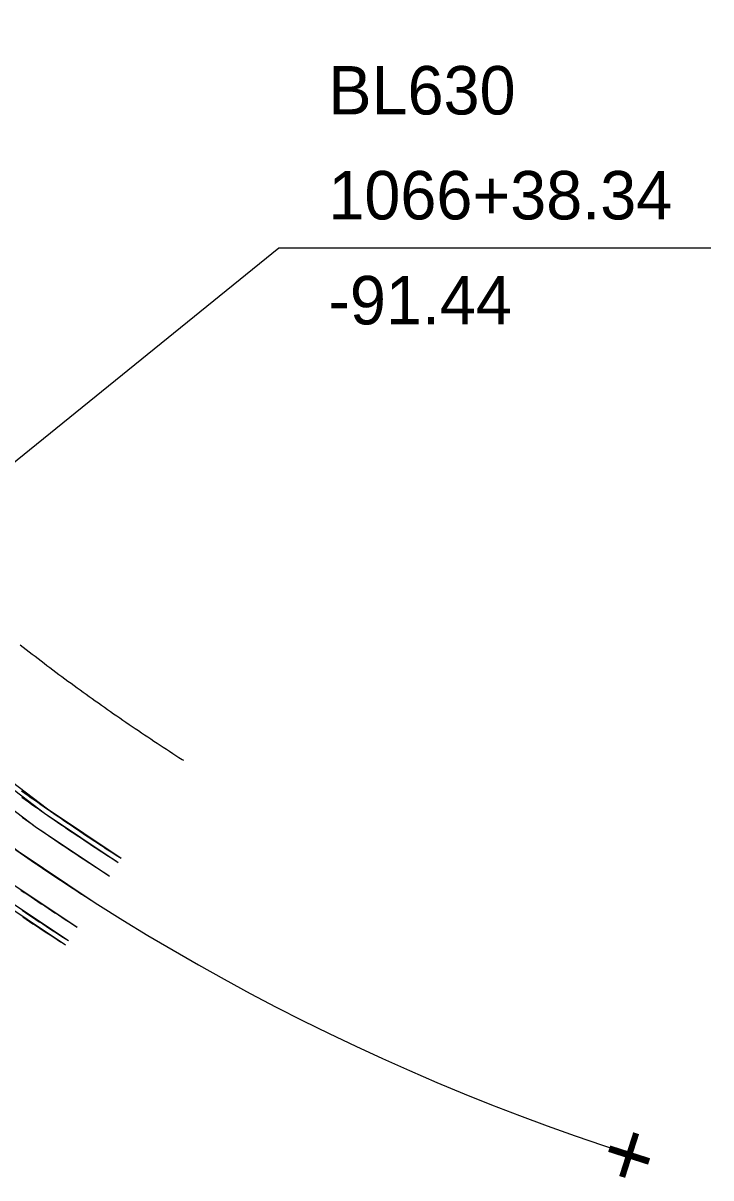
# Model space of a CAD drawing. Extents: x 1195880 to 1289360, y 2059330 to 2086925.
# Drawn here: x 1198545.2 to 1198715.7, y 2069821.4 to 2070107.4 of the extents above; entities that cross this region are included whole.
import ezdxf

# ---------------------------------------------------------------- set-up
doc = ezdxf.new("R2010")
doc.units = 0
for name, color, linetype in [('1', 7, 'Continuous'), ('20', 7, 'Continuous'), ('30', 7, 'Continuous'), ('Pavement', 7, 'Continuous')]:
    doc.layers.add(name, color=color, linetype=linetype)

msp = doc.modelspace()

# ---------------------------------------------------------------- linework, layer by layer
msp.add_line((1198620.61, 2070051.8), (1198715.67, 2070051.8))
msp.add_lwpolyline([(1198483.64, 2069950.58), (1198608.61, 2070051.8), (1198620.61, 2070051.8)])
at = {"layer": '1'}
msp.add_arc((1198871.12, 2070372.64), 572.96, 205.48475, 252.21121, dxfattribs=at)
at = {"layer": '30'}
for points in [[(1198544.51, 2069953.4), (1198545.24, 2069952.83), (1198545.98, 2069952.26), (1198546.71, 2069951.7), (1198547.45, 2069951.13), (1198548.18, 2069950.57), (1198548.92, 2069950.01), (1198549.66, 2069949.44), (1198550.4, 2069948.88), (1198551.14, 2069948.32), (1198551.88, 2069947.77), (1198552.62, 2069947.21), (1198553.36, 2069946.65), (1198554.11, 2069946.1), (1198554.85, 2069945.55), (1198555.6, 2069945), (1198556.34, 2069944.45), (1198557.09, 2069943.9), (1198557.84, 2069943.35), (1198558.59, 2069942.8), (1198559.34, 2069942.26), (1198560.09, 2069941.72), (1198560.85, 2069941.17), (1198561.6, 2069940.63), (1198562.35, 2069940.09), (1198563.11, 2069939.55), (1198563.87, 2069939.02), (1198564.62, 2069938.48), (1198565.38, 2069937.95), (1198566.14, 2069937.42), (1198566.9, 2069936.88), (1198567.66, 2069936.35), (1198568.42, 2069935.82), (1198569.19, 2069935.3), (1198569.95, 2069934.77), (1198570.71, 2069934.25), (1198571.48, 2069933.72), (1198572.25, 2069933.2), (1198573.01, 2069932.68), (1198573.78, 2069932.16), (1198574.55, 2069931.64), (1198575.32, 2069931.12), (1198576.09, 2069930.61), (1198576.87, 2069930.09), (1198577.64, 2069929.58), (1198578.41, 2069929.07), (1198579.19, 2069928.56), (1198579.96, 2069928.05), (1198580.74, 2069927.54), (1198581.52, 2069927.04), (1198582.29, 2069926.53), (1198583.07, 2069926.03), (1198583.85, 2069925.53), (1198584.63, 2069925.03), (1198584.97, 2069924.81)], [(1198544.85, 2069917.26), (1198545.65, 2069916.69), (1198546.44, 2069916.12), (1198547.24, 2069915.55), (1198548.04, 2069914.99), (1198548.84, 2069914.43), (1198549.64, 2069913.86), (1198550.44, 2069913.3), (1198551.24, 2069912.74), (1198552.04, 2069912.19), (1198552.85, 2069911.63), (1198553.65, 2069911.08), (1198554.46, 2069910.52), (1198555.27, 2069909.97), (1198556.07, 2069909.42), (1198556.88, 2069908.87), (1198557.69, 2069908.32), (1198558.5, 2069907.78), (1198559.32, 2069907.23), (1198560.13, 2069906.69), (1198560.94, 2069906.15), (1198561.76, 2069905.61), (1198562.57, 2069905.07), (1198563.39, 2069904.53), (1198564.21, 2069903.99), (1198565.02, 2069903.46), (1198565.84, 2069902.92), (1198566.66, 2069902.39), (1198567.49, 2069901.86), (1198568.31, 2069901.33), (1198569.13, 2069900.8), (1198569.48, 2069900.58)], [(1198544.92, 2069915.67), (1198545.72, 2069915.1), (1198546.52, 2069914.53), (1198547.32, 2069913.97), (1198548.12, 2069913.4), (1198548.92, 2069912.84), (1198549.72, 2069912.28), (1198550.53, 2069911.72), (1198551.33, 2069911.16), (1198552.14, 2069910.6), (1198552.94, 2069910.04), (1198553.75, 2069909.49), (1198554.56, 2069908.94), (1198555.37, 2069908.38), (1198556.18, 2069907.83), (1198556.99, 2069907.29), (1198557.81, 2069906.74), (1198558.62, 2069906.19), (1198559.43, 2069905.65), (1198560.25, 2069905.1), (1198561.07, 2069904.56), (1198561.88, 2069904.02), (1198562.7, 2069903.48), (1198563.52, 2069902.94), (1198564.34, 2069902.41), (1198565.16, 2069901.87), (1198565.98, 2069901.34), (1198566.81, 2069900.81), (1198567.63, 2069900.28), (1198568.46, 2069899.75), (1198568.81, 2069899.52)], [(1198544.97, 2069887.66), (1198545.82, 2069887.09), (1198546.67, 2069886.52), (1198547.52, 2069885.96), (1198548.37, 2069885.39), (1198549.22, 2069884.83), (1198550.07, 2069884.27), (1198550.92, 2069883.71), (1198551.78, 2069883.15), (1198552.63, 2069882.6), (1198553.49, 2069882.04), (1198554.35, 2069881.49), (1198555.2, 2069880.93), (1198556.06, 2069880.38), (1198556.43, 2069880.15)], [(1198545.12, 2069886.05), (1198545.97, 2069885.48), (1198546.82, 2069884.91), (1198547.67, 2069884.34), (1198548.53, 2069883.78), (1198549.38, 2069883.22), (1198550.23, 2069882.66), (1198551.09, 2069882.1), (1198551.95, 2069881.54), (1198552.8, 2069880.98), (1198553.66, 2069880.43), (1198554.52, 2069879.88), (1198555.38, 2069879.32), (1198555.75, 2069879.09)]]:
    msp.add_lwpolyline(points, dxfattribs=at)
at = {"layer": 'Pavement'}
for points in [[(1198303.05, 2070269.36), (1198317.28, 2070222.18), (1198337.85, 2070177.24), (1198359.37, 2070132.1), (1198382.31, 2070088.38), (1198408.94, 2070046.86), (1198439.09, 2070007.82), (1198472.53, 2069971.56), (1198509.01, 2069938.34), (1198548.24, 2069908.44), (1198566.66, 2069896.15)], [(1198303.06, 2070269.36), (1198317.28, 2070222.18), (1198337.86, 2070177.24), (1198359.37, 2070132.1), (1198382.31, 2070088.38), (1198408.94, 2070046.86), (1198439.1, 2070007.82), (1198472.54, 2069971.56), (1198509.01, 2069938.34), (1198548.24, 2069908.44), (1198566.66, 2069896.15)], [(1198306.9, 2070270.46), (1198321.01, 2070223.63), (1198341.47, 2070178.96), (1198362.98, 2070133.82), (1198385.77, 2070090.4), (1198412.21, 2070049.17), (1198442.15, 2070010.4), (1198475.36, 2069974.39), (1198511.57, 2069941.42), (1198550.52, 2069911.72), (1198568.81, 2069899.52)], [(1198308.1, 2070270.81), (1198322.17, 2070224.08), (1198342.59, 2070179.5), (1198364.11, 2070134.36), (1198386.85, 2070091.02), (1198413.23, 2070049.89), (1198443.11, 2070011.21), (1198476.24, 2069975.28), (1198512.37, 2069942.38), (1198551.24, 2069912.75), (1198569.48, 2069900.58)], [(1198295.84, 2070267.29), (1198310.29, 2070219.47), (1198331.08, 2070174.01), (1198352.6, 2070128.87), (1198375.82, 2070084.61), (1198402.81, 2070042.54), (1198433.36, 2070002.98), (1198467.25, 2069966.24), (1198504.21, 2069932.58), (1198543.96, 2069902.28), (1198562.62, 2069889.83)], [(1198283.59, 2070263.78), (1198298.41, 2070214.85), (1198319.58, 2070168.52), (1198341.09, 2070123.39), (1198364.8, 2070078.21), (1198392.39, 2070035.2), (1198423.62, 2069994.76), (1198458.26, 2069957.19), (1198496.04, 2069922.79), (1198536.68, 2069891.81), (1198555.75, 2069879.09)], [(1198284.79, 2070264.13), (1198299.57, 2070215.3), (1198320.71, 2070169.06), (1198342.22, 2070123.93), (1198365.89, 2070078.84), (1198393.42, 2070035.92), (1198424.58, 2069995.57), (1198459.14, 2069958.08), (1198496.84, 2069923.75), (1198537.39, 2069892.84), (1198556.43, 2069880.14)], [(1198288.63, 2070265.23), (1198303.3, 2070216.75), (1198324.31, 2070170.78), (1198345.83, 2070125.65), (1198369.34, 2070080.84), (1198396.68, 2070038.22), (1198427.63, 2069998.14), (1198461.96, 2069960.92), (1198499.4, 2069926.82), (1198539.67, 2069896.12), (1198558.58, 2069883.51)], [(1198288.64, 2070265.23), (1198303.3, 2070216.75), (1198324.32, 2070170.78), (1198345.83, 2070125.65), (1198369.34, 2070080.85), (1198396.68, 2070038.22), (1198427.64, 2069998.15), (1198461.96, 2069960.92), (1198499.4, 2069926.82), (1198539.67, 2069896.12), (1198558.58, 2069883.51)], [(1198544.85, 2069917.26), (1198545.65, 2069916.69), (1198546.44, 2069916.12), (1198547.24, 2069915.55), (1198548.04, 2069914.99), (1198548.84, 2069914.43), (1198549.64, 2069913.86), (1198550.44, 2069913.3), (1198551.24, 2069912.74), (1198552.04, 2069912.19), (1198552.85, 2069911.63), (1198553.65, 2069911.08), (1198554.46, 2069910.52), (1198555.27, 2069909.97), (1198556.07, 2069909.42), (1198556.88, 2069908.87), (1198557.69, 2069908.32), (1198558.5, 2069907.78), (1198559.32, 2069907.23), (1198560.13, 2069906.69), (1198560.94, 2069906.15), (1198561.76, 2069905.61), (1198562.57, 2069905.07), (1198563.39, 2069904.53), (1198564.21, 2069903.99), (1198565.02, 2069903.46), (1198565.84, 2069902.92), (1198566.66, 2069902.39), (1198567.49, 2069901.86), (1198568.31, 2069901.33), (1198569.13, 2069900.8), (1198569.48, 2069900.58)], [(1198544.85, 2069917.25), (1198545.64, 2069916.69), (1198546.44, 2069916.12), (1198547.24, 2069915.55), (1198548.04, 2069914.99), (1198548.84, 2069914.42), (1198549.64, 2069913.86), (1198550.44, 2069913.3), (1198551.24, 2069912.74), (1198552.04, 2069912.19), (1198552.85, 2069911.63), (1198553.65, 2069911.07), (1198554.46, 2069910.52), (1198555.27, 2069909.97), (1198556.07, 2069909.42), (1198556.88, 2069908.87), (1198557.69, 2069908.32), (1198558.5, 2069907.78), (1198559.31, 2069907.23), (1198560.13, 2069906.69), (1198560.94, 2069906.14), (1198561.76, 2069905.6), (1198562.57, 2069905.06), (1198563.39, 2069904.53), (1198564.21, 2069903.99), (1198565.02, 2069903.46), (1198565.84, 2069902.92), (1198566.66, 2069902.39), (1198567.48, 2069901.86), (1198568.31, 2069901.33), (1198569.13, 2069900.8), (1198569.48, 2069900.58)], [(1198544.92, 2069915.67), (1198545.72, 2069915.1), (1198546.52, 2069914.53), (1198547.32, 2069913.97), (1198548.12, 2069913.4), (1198548.92, 2069912.84), (1198549.72, 2069912.28), (1198550.53, 2069911.72), (1198551.33, 2069911.16), (1198552.14, 2069910.6), (1198552.94, 2069910.05), (1198553.75, 2069909.49), (1198554.56, 2069908.94), (1198555.37, 2069908.39), (1198556.18, 2069907.84), (1198556.99, 2069907.29), (1198557.81, 2069906.74), (1198558.62, 2069906.19), (1198559.43, 2069905.65), (1198560.25, 2069905.11), (1198561.07, 2069904.56), (1198561.88, 2069904.02), (1198562.7, 2069903.48), (1198563.52, 2069902.95), (1198564.34, 2069902.41), (1198565.16, 2069901.88), (1198565.98, 2069901.34), (1198566.81, 2069900.81), (1198567.63, 2069900.28), (1198568.46, 2069899.75), (1198568.81, 2069899.52)], [(1198544.92, 2069915.67), (1198545.72, 2069915.1), (1198546.52, 2069914.53), (1198547.32, 2069913.97), (1198548.12, 2069913.4), (1198548.92, 2069912.84), (1198549.72, 2069912.28), (1198550.53, 2069911.72), (1198551.33, 2069911.16), (1198552.14, 2069910.6), (1198552.94, 2069910.04), (1198553.75, 2069909.49), (1198554.56, 2069908.94), (1198555.37, 2069908.38), (1198556.18, 2069907.83), (1198556.99, 2069907.29), (1198557.81, 2069906.74), (1198558.62, 2069906.19), (1198559.43, 2069905.65), (1198560.25, 2069905.1), (1198561.07, 2069904.56), (1198561.88, 2069904.02), (1198562.7, 2069903.48), (1198563.52, 2069902.94), (1198564.34, 2069902.41), (1198565.16, 2069901.87), (1198565.98, 2069901.34), (1198566.81, 2069900.81), (1198567.63, 2069900.28), (1198568.46, 2069899.75), (1198568.81, 2069899.52)], [(1198545.01, 2069910.7), (1198545.82, 2069910.13), (1198546.62, 2069909.56), (1198547.43, 2069909), (1198548.24, 2069908.43), (1198549.05, 2069907.87), (1198549.86, 2069907.31), (1198550.68, 2069906.75), (1198551.49, 2069906.19), (1198552.31, 2069905.63), (1198553.12, 2069905.08), (1198553.94, 2069904.52), (1198554.75, 2069903.97), (1198555.57, 2069903.42), (1198556.39, 2069902.87), (1198557.21, 2069902.32), (1198558.03, 2069901.77), (1198558.86, 2069901.23), (1198559.68, 2069900.68), (1198560.5, 2069900.14), (1198561.33, 2069899.6), (1198562.16, 2069899.06), (1198562.98, 2069898.52), (1198563.81, 2069897.98), (1198564.64, 2069897.45), (1198565.47, 2069896.91), (1198566.3, 2069896.38), (1198566.66, 2069896.15)], [(1198545.01, 2069910.7), (1198545.82, 2069910.13), (1198546.62, 2069909.56), (1198547.43, 2069909), (1198548.24, 2069908.43), (1198549.05, 2069907.87), (1198549.86, 2069907.31), (1198550.68, 2069906.75), (1198551.49, 2069906.19), (1198552.31, 2069905.63), (1198553.12, 2069905.08), (1198553.94, 2069904.52), (1198554.76, 2069903.97), (1198555.57, 2069903.42), (1198556.39, 2069902.87), (1198557.21, 2069902.32), (1198558.03, 2069901.77), (1198558.86, 2069901.23), (1198559.68, 2069900.68), (1198560.5, 2069900.14), (1198561.33, 2069899.6), (1198562.16, 2069899.06), (1198562.98, 2069898.52), (1198563.81, 2069897.98), (1198564.64, 2069897.45), (1198565.47, 2069896.91), (1198566.3, 2069896.38), (1198566.66, 2069896.15)], [(1198545.01, 2069910.7), (1198545.82, 2069910.13), (1198546.62, 2069909.56), (1198547.43, 2069909), (1198548.24, 2069908.43), (1198549.05, 2069907.87), (1198549.86, 2069907.31), (1198550.68, 2069906.75), (1198551.49, 2069906.19), (1198552.31, 2069905.63), (1198553.12, 2069905.08), (1198553.94, 2069904.52), (1198554.76, 2069903.97), (1198555.57, 2069903.42), (1198556.39, 2069902.87), (1198557.21, 2069902.32), (1198558.03, 2069901.77), (1198558.86, 2069901.23), (1198559.68, 2069900.68), (1198560.5, 2069900.14), (1198561.33, 2069899.6), (1198562.16, 2069899.06), (1198562.98, 2069898.52), (1198563.81, 2069897.98), (1198564.64, 2069897.45), (1198565.47, 2069896.91), (1198566.3, 2069896.38), (1198566.66, 2069896.15)], [(1198544.78, 2069901.71), (1198545.6, 2069901.14), (1198546.43, 2069900.57), (1198547.25, 2069900), (1198548.08, 2069899.44), (1198548.9, 2069898.88), (1198549.73, 2069898.31), (1198550.56, 2069897.75), (1198551.39, 2069897.2), (1198552.22, 2069896.64), (1198553.05, 2069896.08), (1198553.88, 2069895.53), (1198554.71, 2069894.97), (1198555.55, 2069894.42), (1198556.38, 2069893.87), (1198557.22, 2069893.32), (1198558.06, 2069892.78), (1198558.9, 2069892.23), (1198559.73, 2069891.69), (1198560.57, 2069891.14), (1198561.41, 2069890.6), (1198562.26, 2069890.06), (1198562.62, 2069889.83)], [(1198544.78, 2069901.71), (1198545.6, 2069901.14), (1198546.43, 2069900.57), (1198547.25, 2069900), (1198548.08, 2069899.44), (1198548.9, 2069898.88), (1198549.73, 2069898.31), (1198550.56, 2069897.75), (1198551.39, 2069897.2), (1198552.22, 2069896.64), (1198553.05, 2069896.08), (1198553.88, 2069895.53), (1198554.71, 2069894.97), (1198555.55, 2069894.42), (1198556.38, 2069893.87), (1198557.22, 2069893.32), (1198558.06, 2069892.78), (1198558.9, 2069892.23), (1198559.73, 2069891.69), (1198560.57, 2069891.14), (1198561.41, 2069890.6), (1198562.26, 2069890.06), (1198562.62, 2069889.83)], [(1198544.68, 2069892.67), (1198545.52, 2069892.1), (1198546.36, 2069891.54), (1198547.2, 2069890.97), (1198548.04, 2069890.41), (1198548.89, 2069889.84), (1198549.73, 2069889.28), (1198550.57, 2069888.72), (1198551.42, 2069888.16), (1198552.26, 2069887.61), (1198553.11, 2069887.05), (1198553.96, 2069886.5), (1198554.81, 2069885.94), (1198555.66, 2069885.39), (1198556.51, 2069884.84), (1198557.36, 2069884.29), (1198558.21, 2069883.75), (1198558.58, 2069883.51)], [(1198544.69, 2069892.68), (1198545.52, 2069892.11), (1198546.36, 2069891.54), (1198547.2, 2069890.97), (1198548.04, 2069890.41), (1198548.89, 2069889.85), (1198549.73, 2069889.28), (1198550.57, 2069888.72), (1198551.42, 2069888.17), (1198552.27, 2069887.61), (1198553.11, 2069887.05), (1198553.96, 2069886.5), (1198554.81, 2069885.94), (1198555.66, 2069885.39), (1198556.51, 2069884.84), (1198557.36, 2069884.3), (1198558.21, 2069883.75), (1198558.58, 2069883.51)], [(1198544.69, 2069892.68), (1198545.52, 2069892.11), (1198546.36, 2069891.54), (1198547.2, 2069890.97), (1198548.05, 2069890.41), (1198548.89, 2069889.85), (1198549.73, 2069889.28), (1198550.57, 2069888.72), (1198551.42, 2069888.17), (1198552.27, 2069887.61), (1198553.11, 2069887.05), (1198553.96, 2069886.5), (1198554.81, 2069885.95), (1198555.66, 2069885.39), (1198556.51, 2069884.84), (1198557.36, 2069884.3), (1198558.22, 2069883.75), (1198558.58, 2069883.51)], [(1198544.97, 2069887.66), (1198545.82, 2069887.09), (1198546.67, 2069886.52), (1198547.52, 2069885.95), (1198548.37, 2069885.39), (1198549.22, 2069884.83), (1198550.07, 2069884.27), (1198550.92, 2069883.71), (1198551.78, 2069883.15), (1198552.63, 2069882.59), (1198553.49, 2069882.04), (1198554.34, 2069881.48), (1198555.2, 2069880.93), (1198556.06, 2069880.38), (1198556.43, 2069880.14)], [(1198544.97, 2069887.66), (1198545.82, 2069887.09), (1198546.67, 2069886.52), (1198547.52, 2069885.96), (1198548.37, 2069885.39), (1198549.22, 2069884.83), (1198550.07, 2069884.27), (1198550.92, 2069883.71), (1198551.78, 2069883.15), (1198552.63, 2069882.6), (1198553.49, 2069882.04), (1198554.35, 2069881.49), (1198555.2, 2069880.93), (1198556.06, 2069880.38), (1198556.43, 2069880.15)], [(1198545.12, 2069886.05), (1198545.97, 2069885.48), (1198546.82, 2069884.91), (1198547.67, 2069884.35), (1198548.53, 2069883.78), (1198549.38, 2069883.22), (1198550.24, 2069882.66), (1198551.09, 2069882.1), (1198551.95, 2069881.54), (1198552.81, 2069880.99), (1198553.66, 2069880.43), (1198554.52, 2069879.88), (1198555.38, 2069879.33), (1198555.75, 2069879.09)], [(1198545.12, 2069886.05), (1198545.97, 2069885.48), (1198546.82, 2069884.91), (1198547.67, 2069884.34), (1198548.53, 2069883.78), (1198549.38, 2069883.22), (1198550.23, 2069882.66), (1198551.09, 2069882.1), (1198551.95, 2069881.54), (1198552.8, 2069880.98), (1198553.66, 2069880.43), (1198554.52, 2069879.88), (1198555.38, 2069879.32), (1198555.75, 2069879.09)]]:
    msp.add_lwpolyline(points, dxfattribs=at)

# ---------------------------------------------------------------- texts
at = {"layer": '20'}
for s, p in [('BL630', (1198620.86, 2070084.8)), ('1066+38.34', (1198620.86, 2070058.8)), ('-91.44', (1198620.86, 2070032.8))]:
    msp.add_text(s, height=12, dxfattribs=at).set_placement(p)
msp.add_text('+', height=16, rotation=342.2112, dxfattribs=at).set_placement((1198687.1, 2069821.56))

doc.saveas('drawing.dxf')
